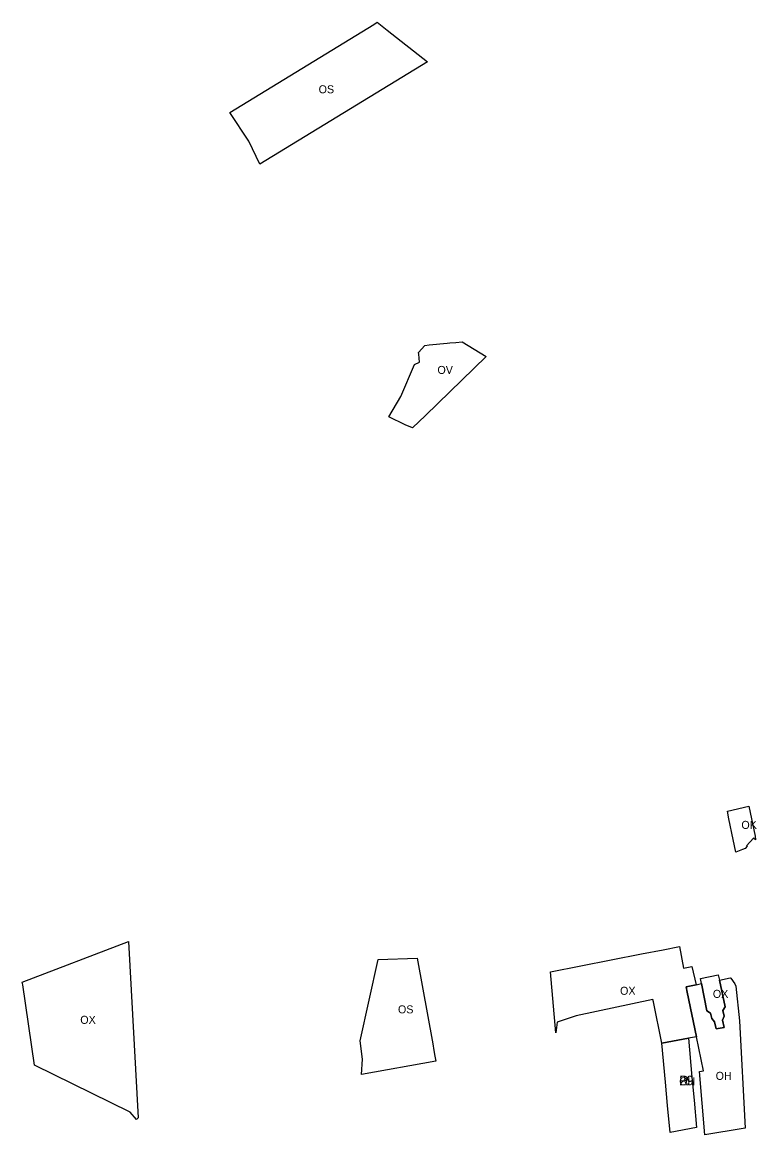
# Model space of a CAD drawing. Extents: x -520747 to -519285, y -1141727 to -1140602.
import ezdxf

# ---------------------------------------------------------------- set-up
doc = ezdxf.new("R2010")
doc.units = 0
for name, color, linetype in [('90140013', 7, 'Continuous'), ('90210013', 7, 'Continuous'), ('90210033', 7, 'Continuous'), ('90220013', 7, 'Continuous'), ('90290013', 7, 'Continuous'), ('90300013', 7, 'Continuous'), ('ID_rezerva', 7, 'Continuous'), ('ID_rezervaR', 7, 'Continuous')]:
    doc.layers.add(name, color=color, linetype=linetype)

msp = doc.modelspace()

# ---------------------------------------------------------------- linework, layer by layer
at = {"layer": '90140013'}
msp.add_lwpolyline([(-520456.93, -1140810.9), (-520494.89, -1140847.8), (-520502.85, -1140855.53), (-520507.49, -1140853.67), (-520517.77, -1140848.71), (-520510.31, -1140835.9), (-520501.75, -1140815.97), (-520498.5, -1140814.52), (-520499.02, -1140809.41), (-520499.12, -1140808.43), (-520495.25, -1140804.01), (-520492.42, -1140803.71), (-520481.31, -1140802.54), (-520479.52, -1140802.35), (-520475.9, -1140802.08), (-520471.87, -1140801.78)], close=True, dxfattribs=at)
at = {"layer": '90210013'}
msp.add_lwpolyline([(-520325.59, -1141235.8), (-520331.36, -1141208.07), (-520332.09, -1141204.58), (-520325.76, -1141203.31), (-520322.39, -1141202.63), (-520319.07, -1141219.54), (-520316.76, -1141221.12), (-520316.06, -1141224.47), (-520314.28, -1141226.51), (-520313.3, -1141230.91), (-520308.37, -1141230.04), (-520309.23, -1141225.55), (-520308.34, -1141222.91), (-520309.05, -1141219.45), (-520307.6, -1141217.21), (-520311.28, -1141200.4), (-520304.49, -1141199.02), (-520304.21, -1141199.32), (-520301.55, -1141202.8), (-520300.95, -1141204.15), (-520298.61, -1141225.85), (-520295.11, -1141292.82), (-520296.48, -1141293.05), (-520320.29, -1141297.03), (-520323.62, -1141257.49), (-520321.16, -1141257.11)], close=True, dxfattribs=at)
at = {"layer": '90210033'}
msp.add_lwpolyline([(-520328.39, -1141261.02), (-520327.05, -1141275.53), (-520325.5, -1141292.44), (-520342.05, -1141295.55), (-520343.6, -1141278.76), (-520344.95, -1141264.09), (-520347.19, -1141239.81), (-520330.62, -1141236.74)], close=True, dxfattribs=at)
at = {"layer": '90220013'}
msp.add_lwpolyline([(-520300.97, -1141120.47), (-520302.64, -1141112.56), (-520305.34, -1141099.75), (-520306.28, -1141094.87), (-520292.97, -1141091.81), (-520289, -1141110.56), (-520288.75, -1141112.92), (-520290.03, -1141111.68), (-520294.23, -1141116.47), (-520293.88, -1141116.78), (-520295.14, -1141118.22), (-520296.78, -1141118.85)], close=True, dxfattribs=at)
at = {"layer": '90290013'}
for points in [[(-520525.02, -1140602.15), (-520518.65, -1140607.14), (-520493.55, -1140626.8), (-520598.21, -1140690.89), (-520605.12, -1140676.44), (-520617.05, -1140658.61), (-520527.15, -1140603.46)], [(-520488.89, -1141247.94), (-520488.31, -1141251.1), (-520534.84, -1141259.42), (-520534.05, -1141249.88), (-520535.7, -1141238.47), (-520524.27, -1141187.6), (-520500.08, -1141186.63), (-520490.28, -1141240.29), (-520489.54, -1141244.37)]]:
    msp.add_lwpolyline(points, close=True, dxfattribs=at)
at = {"layer": '90300013'}
for points in [[(-520675.31, -1141287.41), (-520679.28, -1141282.96), (-520739.03, -1141253.62), (-520746.38, -1141203.48), (-520746.65, -1141201.66), (-520680.34, -1141176.38), (-520674.18, -1141286.49)], [(-520325.59, -1141235.8), (-520330.62, -1141236.74), (-520347.19, -1141239.81), (-520352.46, -1141213.96), (-520352.51, -1141213.97), (-520352.78, -1141212.63), (-520400.61, -1141222.82), (-520412.54, -1141226.76), (-520413.51, -1141233.43), (-520416.76, -1141195.21), (-520359.99, -1141184.11), (-520346.46, -1141181.44), (-520336.24, -1141179.42), (-520333.6, -1141192.88), (-520328.4, -1141191.92), (-520325.76, -1141203.31), (-520332.09, -1141204.58), (-520331.36, -1141208.07)], [(-520311.28, -1141200.4), (-520307.6, -1141217.21), (-520309.05, -1141219.45), (-520308.34, -1141222.91), (-520309.23, -1141225.55), (-520308.37, -1141230.04), (-520313.3, -1141230.91), (-520314.28, -1141226.51), (-520316.06, -1141224.47), (-520316.76, -1141221.12), (-520319.07, -1141219.54), (-520322.39, -1141202.63), (-520323.1, -1141199.37), (-520312, -1141197.1)]]:
    msp.add_lwpolyline(points, close=True, dxfattribs=at)

# ---------------------------------------------------------------- texts
at = {"layer": '90140013'}
msp.add_text('OV', height=5, rotation=0, dxfattribs=at).set_placement((-520487.35, -1140821.82))
at = {"layer": '90210013'}
msp.add_text('OH', height=5, rotation=360, dxfattribs=at).set_placement((-520313.6, -1141262.74))
at = {"layer": '90210033'}
msp.add_text('OH', height=5, rotation=360, dxfattribs=at).set_placement((-520336.34, -1141266.14))
at = {"layer": '90220013'}
msp.add_text('OK', height=5, rotation=360, dxfattribs=at).set_placement((-520297.52, -1141105.99))
at = {"layer": '90290013'}
for p in [(-520561.55, -1140646.52), (-520512, -1141221.22)]:
    msp.add_text('OS', height=5, rotation=0, dxfattribs=at).set_placement(p)
at = {"layer": '90300013'}
for rotation, p in [(360, (-520373.29, -1141209.61)), (360, (-520315.35, -1141211.53)), (0, (-520710.41, -1141227.76))]:
    msp.add_text('OX', height=5, rotation=rotation, dxfattribs=at).set_placement(p)
at = {"layer": 'ID_rezerva'}
msp.add_text('29', height=6, rotation=360, dxfattribs=at).set_placement((-520336.34, -1141266.14))
at = {"layer": 'ID_rezervaR'}
msp.add_text('R', height=6, rotation=360, dxfattribs=at).set_placement((-520336.34, -1141266.14))

doc.saveas('drawing.dxf')
